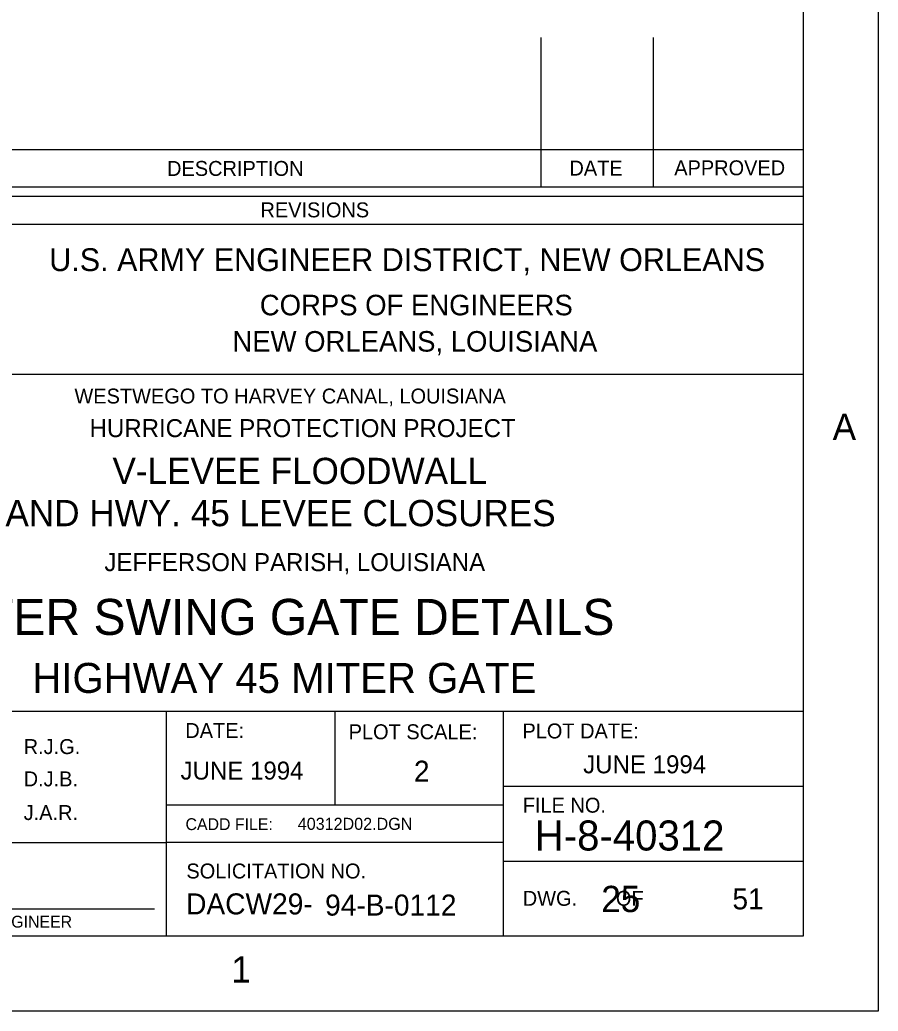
# Model space of a CAD drawing. Extents: x 0.04 to 6.71, y 0.04 to 4.71.
# Drawn here: x 5.754 to 6.708, y 0.042 to 1.145 of the extents above; entities that cross this region are included whole.
import ezdxf

# ---------------------------------------------------------------- set-up
doc = ezdxf.new("R2010")
doc.units = 0
doc.layers.add('Level 1', color=7, linetype='Continuous')
doc.layers.add('Level 2', color=7, linetype='Continuous')

msp = doc.modelspace()

# ---------------------------------------------------------------- linework, layer by layer
at = {"layer": 'Level 1'}
for p, q in [((6.3333, 0.9583), (6.3333, 1.125)), ((6.4583, 0.9583), (6.4583, 1.125)), ((6.625, 1), (5.5417, 1)), ((6.625, 0.9583), (5.5417, 0.9583)), ((6.625, 0.9479), (5.5417, 0.9479)), ((6.625, 0.9167), (5.5417, 0.9167)), ((6.625, 0.75), (5.5417, 0.75)), ((6.625, 0.375), (5.5417, 0.375)), ((5.9167, 0.125), (5.9167, 0.375)), ((6.1042, 0.2708), (6.1042, 0.375)), ((6.2917, 0.125), (6.2917, 0.375)), ((6.625, 0.2917), (6.2917, 0.2917)), ((6.2917, 0.2708), (5.9167, 0.2708)), ((5.5417, 0.2292), (5.9167, 0.2292)), ((6.2917, 0.2292), (5.9167, 0.2292)), ((6.625, 0.2083), (6.2917, 0.2083)), ((5.5529, 0.1556), (5.9034, 0.1556))]:
    msp.add_line(p, q, dxfattribs=at)
for points in [[(0.0417, 4.7083), (6.7083, 4.7083), (6.7083, 0.0417), (0.0417, 0.0417)], [(0.2917, 4.625), (6.625, 4.625), (6.625, 0.125), (0.2917, 0.125)]]:
    msp.add_lwpolyline(points, close=True, dxfattribs=at)

# ---------------------------------------------------------------- texts
for s, height, p in [('DESCRIPTION', 0.016604, (5.9173, 0.9709)), ('DATE', 0.0166, (6.3649, 0.9713)), ('APPROVED', 0.0166, (6.4815, 0.9716)), ('REVISIONS', 0.0166, (6.0212, 0.9248)), ('U.S. ARMY ENGINEER DISTRICT, NEW ORLEANS', 0.025396, (5.7862, 0.865)), ('CORPS OF ENGINEERS', 0.022856, (6.0205, 0.8158)), ('NEW ORLEANS, LOUISIANA', 0.022856, (5.99, 0.7754)), ('A', 0.0292, (6.6577, 0.6772)), ('DATE:', 0.0166, (5.9376, 0.3456)), ('PLOT SCALE:', 0.016604, (6.1193, 0.3442)), ('PLOT DATE:', 0.0166, (6.3126, 0.3451)), ('FILE NO.', 0.0166, (6.313, 0.2625)), ('CADD FILE:', 0.01321, (5.9378, 0.2431)), ('SOLICITATION NO.', 0.016604, (5.9388, 0.1893)), ('DACW29-', 0.0234, (5.9385, 0.1493)), ('DWG.       OF', 0.016604, (6.313, 0.1589)), ('DESIGN ENGINEER', 0.013208, (5.6468, 0.1346)), ('1', 0.0292, (5.9888, 0.0735))]:
    msp.add_text(s, height=height, dxfattribs=at).set_placement(p)
at = {"layer": 'Level 2'}
for s, height, p in [('WESTWEGO TO HARVEY CANAL, LOUISIANA', 0.016604, (5.8143, 0.7177)), ('HURRICANE PROTECTION PROJECT', 0.02, (5.8311, 0.6803)), ('V-LEVEE FLOODWALL', 0.029208, (5.8566, 0.6281)), ('AND HWY. 45 LEVEE CLOSURES', 0.029208, (5.7375, 0.5812)), ('JEFFERSON PARISH, LOUISIANA', 0.02, (5.8476, 0.5312)), ('MITER SWING GATE DETAILS', 0.04, (5.6542, 0.4603)), ('HIGHWAY 45 MITER GATE', 0.033396, (5.7674, 0.3957)), ('R.J.G.', 0.0166, (5.7578, 0.3277)), ('2', 0.0234, (6.1919, 0.2969)), ('JUNE 1994', 0.02, (6.3802, 0.3063)), ('JUNE 1994', 0.02, (5.9323, 0.2993)), ('D.J.B.', 0.0166, (5.7578, 0.2918)), ('J.A.R.', 0.0166, (5.7578, 0.2543)), ('40312D02.DGN', 0.013396, (6.0627, 0.2434)), ('H-8-40312', 0.0334, (6.3263, 0.2204)), ('25', 0.02921, (6.4003, 0.1519)), ('51', 0.0234, (6.5462, 0.1549)), ('94-B-0112', 0.0234, (6.0931, 0.148))]:
    msp.add_text(s, height=height, dxfattribs=at).set_placement(p)

doc.saveas('drawing.dxf')
